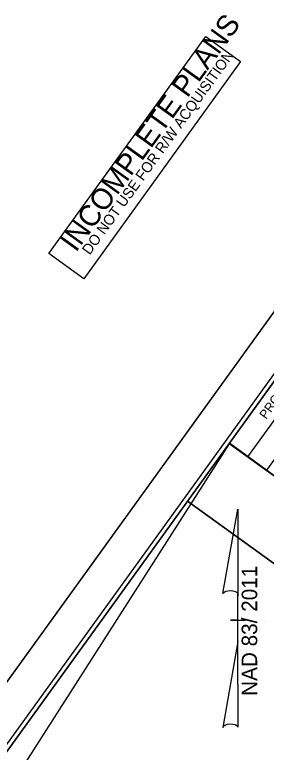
# Model space of a CAD drawing. Extents: x 2189185 to 2191058, y 386509 to 388561.
# Drawn here: x 2189943.6 to 2190081.4, y 388156.8 to 388561.4 of the extents above; entities that cross this region are included whole.
import ezdxf

# ---------------------------------------------------------------- set-up
doc = ezdxf.new("R2010")
doc.units = 0
for name, color, linetype in [('Prop North Arrow NAD83 for Plan Sheets CELL', 7, 'Continuous'), ('Sheet Clip Boundary CELL', 7, 'Continuous'), ('Sheet Cutting Line CELL', 7, 'Continuous'), ('Sheet Layout Plan Border', 7, 'Continuous'), ('Sheet North Arrow Point CELL', 7, 'Continuous'), ('Sheet Plan CELL', 7, 'Continuous'), ('Sheet Plan Layout CELL', 7, 'Continuous'), ('Sheet Plot Border Inside CELL', 7, 'Continuous'), ('Sheet Plot Border Outside CELL', 7, 'Continuous'), ('Sheet Sticker Incomplete CELL', 7, 'Continuous')]:
    doc.layers.add(name, color=color, linetype=linetype)

msp = doc.modelspace()

# ---------------------------------------------------------------- linework, layer by layer
at = {"layer": 'Prop North Arrow NAD83 for Plan Sheets CELL'}
for p, q in [((2190057.65, 388243.86), (2190065.85, 388290.21)), ((2190065.9, 388290.21), (2190065.85, 388290.21)), ((2190065.9, 388290.21), (2190065.85, 388290.21)), ((2190065.9, 388290.21), (2190065.9, 388242.41)), ((2190065.9, 388217.61), (2190065.9, 388243.81)), ((2190065.9, 388242.41), (2190065.9, 388243.76)), ((2190061.9, 388229.21), (2190061.85, 388229.21)), ((2190065.45, 388229.21), (2190061.9, 388229.21)), ((2190061.95, 388229.21), (2190069.95, 388229.21)), ((2190065.9, 388217.61), (2190057.55, 388170.36)), ((2190065.95, 388170.56), (2190065.9, 388217.61))]:
    msp.add_line(p, q, dxfattribs=at)
for centre, start_param, end_param in [((2190061.79, 388243.36), 0.216388, 2.908219), ((2190061.79, 388170.19), 0.201328, 3.141593)]:
    msp.add_ellipse(centre, major_axis=(4.23, -0.03), ratio=0.461098, start_param=start_param, end_param=end_param, dxfattribs=at)
at = {"layer": 'Sheet Clip Boundary CELL'}
msp.add_lwpolyline([(2190166.8, 386710.01), (2190905.33, 387738.93), (2190256.9, 388232.77), (2190233.39, 388201.76), (2190061.07, 388326.03), (2189853.58, 388001.31), (2189912.61, 387915.43), (2189757.61, 387710.51), (2189654.64, 387750.49), (2189330.08, 387312.42)], close=True, dxfattribs=at)
at = {"layer": 'Sheet Cutting Line CELL'}
msp.add_line((2190169.94, 388515.44), (2189185.21, 387149.98), dxfattribs=at)
at = {"layer": 'Sheet Layout Plan Border'}
msp.add_lwpolyline([(2190181.72, 386698.24), (2191000.63, 387833.76), (2190320.53, 388324.24), (2190209.82, 388170.73), (2190038.29, 388294.44), (2189330.08, 387312.42)], close=True, dxfattribs=at)
at = {"layer": 'Sheet North Arrow Point CELL'}
msp.add_line((2190080.57, 388228.37), (2190080.57, 388228.37), dxfattribs=at)
at = {"layer": 'Sheet Plan CELL'}
msp.add_line((2190071.39, 388318.9), (2190188.41, 388481.15), dxfattribs=at)
for points in [[(2190178.25, 388488.52), (2189300.83, 387271.86), (2190152.47, 386657.68), (2191029.88, 387874.32)], [(2190061.21, 388326.25), (2190178.25, 388488.52), (2190198.55, 388473.83), (2190081.56, 388311.57)], [(2190152.47, 386657.68), (2189300.84, 387271.83), (2190061.21, 388326.25), (2190182.93, 388238.48), (2190299.95, 388400.72), (2191029.88, 387874.32)]]:
    msp.add_lwpolyline(points, close=True, dxfattribs=at)
at = {"layer": 'Sheet Plan Layout CELL'}
for points in [[(2190209.82, 388170.73), (2190349.78, 388364.8), (2190178.26, 388488.53), (2190038.29, 388294.44)], [(2189300.84, 387271.83), (2190152.47, 386657.68), (2191029.87, 387874.31), (2190349.77, 388364.78), (2190209.82, 388170.73), (2190038.29, 388294.44)]]:
    msp.add_lwpolyline(points, close=True, dxfattribs=at)
at = {"layer": 'Sheet Plot Border Inside CELL'}
msp.add_lwpolyline([(2190064.73, 386531.72), (2191039.21, 387882.98), (2190183.53, 388500.09), (2189209.04, 387148.83)], close=True, dxfattribs=at)
at = {"layer": 'Sheet Plot Border Outside CELL'}
msp.add_lwpolyline([(2190073.35, 386509.48), (2191058.08, 387874.94), (2190169.94, 388515.44), (2189185.21, 387149.98)], close=True, dxfattribs=at)
at = {"layer": 'Sheet Sticker Incomplete CELL'}
msp.add_lwpolyline([(2189981.37, 388416.56), (2189962.31, 388430.31), (2190048.29, 388549.54), (2190067.35, 388535.79)], close=True, dxfattribs=at)

# ---------------------------------------------------------------- texts
at = {"layer": 'Prop North Arrow NAD83 for Plan Sheets CELL'}
msp.add_text('NAD 83/ 2011', height=8.5, rotation=90, dxfattribs=at).set_placement((2190076.42, 388187.69))
at = {"layer": 'Sheet Plan CELL'}
msp.add_text('PROJECT REFERENCE NO.', height=5.0001, rotation=54.2018, dxfattribs=at).set_placement((2190081.28, 388339.15))
at = {"layer": 'Sheet Sticker Incomplete CELL'}
for s, height, p in [('INCOMPLETE PLANS', 11.52, (2189977.11, 388430.67)), ('DO NOT USE FOR R/W ACQUISITION', 5.76, (2189984.65, 388429.24))]:
    msp.add_text(s, height=height, rotation=54.2018, dxfattribs=at).set_placement(p)

doc.saveas('drawing.dxf')
